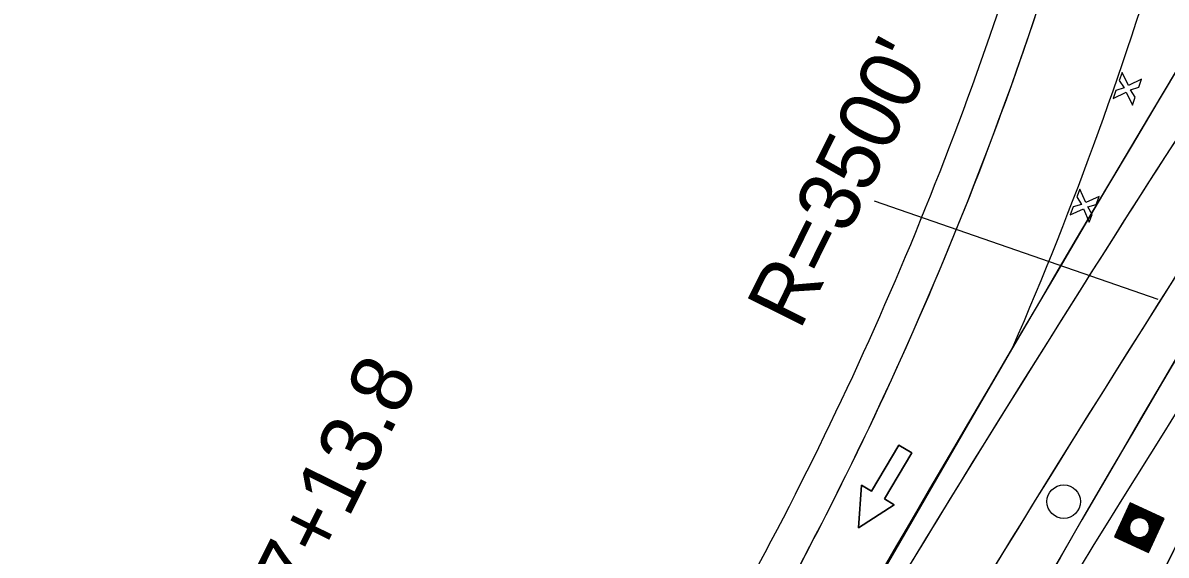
# Model space of a CAD drawing. Extents: x 14104283 to 14129344, y 8637090 to 8673339.
# Drawn here: x 14118812.8 to 14119000.1, y 8668623.1 to 8668710.3 of the extents above; entities that cross this region are included whole.
import ezdxf

# ---------------------------------------------------------------- set-up
doc = ezdxf.new("R2010")
doc.units = 0
for name, color, linetype in [('Cell', 7, 'Continuous'), ('dsnCellElements', 7, 'Continuous'), ('dsnPaintExistingBrokenLaneLineWhite', 7, 'Continuous'), ('dsnPaintExistingChannelizingLaneWhite', 7, 'Continuous'), ('dsnPaintExistingEdgeLineRightWhite', 7, 'Continuous'), ('dsnPaintExistingLaneLineWhite', 7, 'Continuous'), ('dsnShadingPaved', 7, 'Continuous'), ('dsnStdLabel', 7, 'Continuous'), ('dsnStgShadingPrevPav', 7, 'Continuous'), ('dsnTapeExistingChannelizingLaneWhite', 7, 'Continuous'), ('dsnTapeExistingChannelizingLaneYellow', 7, 'Continuous'), ('dsnTapePlaceChannelizingLaneWhite', 7, 'Continuous'), ('dsnTapePlaceChannelizingLaneYellow', 7, 'Continuous'), ('dsnTapeRemoveChannelizingYellow', 7, 'Continuous'), ('Level 2', 7, 'Continuous'), ('Level 5', 7, 'Continuous')]:
    doc.layers.add(name, color=color, linetype=linetype)

msp = doc.modelspace()

# ---------------------------------------------------------------- linework, layer by layer
at = {"layer": 'Cell'}
for p, q in [((14118992.87, 8668702.17), (14118992.42, 8668700.87)), ((14118993.92, 8668700.02), (14118992.87, 8668702.17)), ((14118993.2, 8668699.67), (14118991.85, 8668699.21)), ((14118992.42, 8668700.87), (14118993.2, 8668699.67)), ((14118996.06, 8668701.07), (14118993.92, 8668700.02)), ((14118994.26, 8668699.31), (14118995.61, 8668699.77)), ((14118995.61, 8668699.77), (14118996.06, 8668701.07)), ((14118991.85, 8668699.21), (14118991.4, 8668697.91)), ((14118991.4, 8668697.91), (14118993.55, 8668698.96)), ((14118993.55, 8668698.96), (14118994.6, 8668696.81)), ((14118995.04, 8668698.11), (14118994.26, 8668699.31)), ((14118994.6, 8668696.81), (14118995.04, 8668698.11)), ((14118985.98, 8668683.07), (14118985.49, 8668681.79)), ((14118986.95, 8668680.89), (14118985.98, 8668683.07)), ((14118985.49, 8668681.79), (14118986.22, 8668680.56)), ((14118989.13, 8668681.85), (14118986.95, 8668680.89)), ((14118988.63, 8668680.57), (14118989.13, 8668681.85)), ((14118984.85, 8668680.15), (14118984.36, 8668678.87)), ((14118984.36, 8668678.87), (14118986.54, 8668679.84)), ((14118986.22, 8668680.56), (14118984.85, 8668680.15)), ((14118986.54, 8668679.84), (14118987.51, 8668677.65)), ((14118987.27, 8668680.16), (14118988.63, 8668680.57)), ((14118988, 8668678.94), (14118987.27, 8668680.16)), ((14118987.51, 8668677.65), (14118988, 8668678.94))]:
    msp.add_line(p, q, dxfattribs=at)
msp.add_circle((14118983.32, 8668631.9), 2.75, dxfattribs=at)
at = {"layer": 'dsnCellElements'}
msp.add_circle((14118995.72, 8668627.63), 1.65, dxfattribs=at)
at = {"layer": 'dsnPaintExistingBrokenLaneLineWhite'}
for centre, radius, start, end in [((14121592.11, 8667345.68), 2864.95, 147.15737, 157.1633), ((14121955.85, 8666791.92), 3500, 144.95493, 149.50762)]:
    msp.add_arc(centre, radius, start, end, dxfattribs=at)
at = {"layer": 'dsnPaintExistingChannelizingLaneWhite'}
msp.add_arc((14118409.81, 8668902.17), 616, 336.56541, 343.63038, dxfattribs=at)
at = {"layer": 'dsnPaintExistingEdgeLineRightWhite'}
for centre, radius, start, end in [((14121592.11, 8667345.68), 2852.95, 147.15737, 157.1633), ((14118409.81, 8668902.17), 600, 334.79009, 343.63038), ((14118421.29, 8668896.21), 587.08, 330.32024, 334.83876)]:
    msp.add_arc(centre, radius, start, end, dxfattribs=at)
at = {"layer": 'dsnPaintExistingLaneLineWhite'}
msp.add_arc((14122745.39, 8666422.79), 4382.73, 149.34837, 152.56312, dxfattribs=at)
at = {"layer": 'dsnShadingPaved'}
for centre, radius, start, end in [((14121955.85, 8666791.92), 3512, 144.95493, 152.69211), ((14121955.85, 8666791.92), 3500, 144.95493, 152.69211), ((14121592.11, 8667345.68), 2888.95, 151.24538, 156.90337), ((14118409.81, 8668902.17), 600, 330.3689, 343.63038), ((14121592.11, 8667345.68), 2876.95, 151.24538, 156.90337), ((14118409.81, 8668902.17), 616, 336.56541, 343.63038), ((14123732.96, 8665874.38), 5512, 149.67774, 156.09858)]:
    msp.add_arc(centre, radius, start, end, dxfattribs=at)
at = {"layer": 'dsnStdLabel'}
msp.add_line((14118952.26, 8668681.14), (14118998.75, 8668665.07), dxfattribs=at)
for points in [[(14118997.21, 8668623.56), (14118999.79, 8668629.12), (14118994.23, 8668631.69), (14118991.65, 8668626.13), (14118997.21, 8668623.56)], [(14118997.21, 8668623.56), (14118999.78, 8668629.12), (14118994.23, 8668631.69), (14118991.66, 8668626.14), (14118997.21, 8668623.56)], [(14118997.21, 8668623.56), (14118999.78, 8668629.12), (14118994.23, 8668631.68), (14118991.66, 8668626.14), (14118997.22, 8668623.57)], [(14118997.23, 8668623.7), (14118999.73, 8668629.1), (14118994.25, 8668631.64), (14118991.71, 8668626.15), (14118997.23, 8668623.6)], [(14118997.22, 8668623.75), (14118999.69, 8668629.08), (14118994.26, 8668631.6), (14118991.75, 8668626.17), (14118997.24, 8668623.63)], [(14118997.2, 8668623.79), (14118999.65, 8668629.07), (14118994.28, 8668631.55), (14118991.79, 8668626.19), (14118997.26, 8668623.66)], [(14118997.19, 8668623.83), (14118999.6, 8668629.05), (14118994.29, 8668631.51), (14118991.84, 8668626.2), (14118997.23, 8668623.7)], [(14118997.17, 8668623.88), (14118999.56, 8668629.04), (14118994.31, 8668631.47), (14118991.88, 8668626.22), (14118997.22, 8668623.75)], [(14118997.15, 8668623.92), (14118999.51, 8668629.02), (14118994.33, 8668631.42), (14118991.93, 8668626.23), (14118997.2, 8668623.79)], [(14118997.14, 8668623.97), (14118999.47, 8668629), (14118994.34, 8668631.38), (14118991.97, 8668626.25), (14118997.19, 8668623.83)], [(14118997.12, 8668624.01), (14118999.43, 8668628.99), (14118994.36, 8668631.33), (14118992.01, 8668626.27), (14118997.17, 8668623.88)], [(14118997.11, 8668624.05), (14118999.38, 8668628.97), (14118994.38, 8668631.29), (14118992.06, 8668626.28), (14118997.15, 8668623.92)], [(14118997.09, 8668624.1), (14118999.34, 8668628.96), (14118994.39, 8668631.25), (14118992.1, 8668626.3), (14118997.14, 8668623.97)], [(14118997.07, 8668624.14), (14118999.3, 8668628.94), (14118994.41, 8668631.2), (14118992.14, 8668626.31), (14118997.12, 8668624.01)], [(14118997.06, 8668624.18), (14118999.25, 8668628.92), (14118994.42, 8668631.16), (14118992.19, 8668626.33), (14118997.11, 8668624.05)], [(14118997.04, 8668624.23), (14118999.21, 8668628.91), (14118994.44, 8668631.11), (14118992.23, 8668626.35), (14118997.09, 8668624.1)], [(14118997.03, 8668624.27), (14118999.16, 8668628.89), (14118994.46, 8668631.07), (14118992.28, 8668626.36), (14118997.07, 8668624.14)], [(14118997.01, 8668624.32), (14118999.12, 8668628.87), (14118994.47, 8668631.03), (14118992.32, 8668626.38), (14118997.06, 8668624.18)], [(14118996.99, 8668624.36), (14118999.08, 8668628.86), (14118994.49, 8668630.98), (14118992.36, 8668626.39), (14118997.04, 8668624.23)], [(14118996.98, 8668624.4), (14118999.03, 8668628.84), (14118994.5, 8668630.94), (14118992.41, 8668626.41), (14118997.03, 8668624.27)], [(14118996.96, 8668624.45), (14118998.99, 8668628.83), (14118994.52, 8668630.9), (14118992.45, 8668626.43), (14118997.01, 8668624.32)], [(14118996.95, 8668624.49), (14118998.94, 8668628.81), (14118994.54, 8668630.85), (14118992.49, 8668626.44), (14118996.99, 8668624.36)], [(14118996.93, 8668624.54), (14118998.9, 8668628.79), (14118994.55, 8668630.81), (14118992.54, 8668626.46), (14118996.98, 8668624.4)], [(14118996.91, 8668624.58), (14118998.86, 8668628.78), (14118994.57, 8668630.76), (14118992.58, 8668626.48), (14118996.96, 8668624.45)], [(14118996.9, 8668624.62), (14118998.81, 8668628.76), (14118994.58, 8668630.72), (14118992.63, 8668626.49), (14118996.95, 8668624.49)], [(14118996.88, 8668624.67), (14118998.77, 8668628.75), (14118994.6, 8668630.68), (14118992.67, 8668626.51), (14118996.93, 8668624.54)], [(14118996.86, 8668624.71), (14118998.73, 8668628.73), (14118994.62, 8668630.63), (14118992.71, 8668626.52), (14118996.91, 8668624.58)], [(14118996.85, 8668624.75), (14118998.68, 8668628.71), (14118994.63, 8668630.59), (14118992.76, 8668626.54), (14118996.9, 8668624.62)], [(14118996.83, 8668624.8), (14118998.64, 8668628.7), (14118994.65, 8668630.55), (14118992.8, 8668626.56), (14118996.88, 8668624.67)], [(14118996.82, 8668624.84), (14118998.59, 8668628.68), (14118994.66, 8668630.5), (14118992.85, 8668626.57), (14118996.86, 8668624.71)], [(14118996.8, 8668624.89), (14118998.55, 8668628.67), (14118994.68, 8668630.46), (14118992.89, 8668626.59), (14118996.85, 8668624.75)], [(14118996.78, 8668624.93), (14118998.51, 8668628.65), (14118994.7, 8668630.41), (14118992.93, 8668626.6), (14118996.83, 8668624.8)], [(14118996.77, 8668624.97), (14118998.46, 8668628.63), (14118994.71, 8668630.37), (14118992.98, 8668626.62), (14118996.82, 8668624.84)], [(14118996.75, 8668625.02), (14118998.42, 8668628.62), (14118994.73, 8668630.33), (14118993.02, 8668626.64), (14118996.8, 8668624.89)], [(14118996.74, 8668625.06), (14118998.38, 8668628.6), (14118994.74, 8668630.28), (14118993.06, 8668626.65), (14118996.78, 8668624.93)], [(14118996.72, 8668625.11), (14118998.33, 8668628.59), (14118994.76, 8668630.24), (14118993.11, 8668626.67), (14118996.77, 8668624.97)], [(14118996.7, 8668625.15), (14118998.29, 8668628.57), (14118994.78, 8668630.19), (14118993.15, 8668626.68), (14118996.75, 8668625.02)], [(14118996.69, 8668625.19), (14118998.24, 8668628.55), (14118994.79, 8668630.15), (14118993.2, 8668626.7), (14118996.74, 8668625.06)], [(14118996.67, 8668625.24), (14118998.2, 8668628.54), (14118994.81, 8668630.11), (14118993.24, 8668626.72), (14118996.72, 8668625.11)], [(14118996.66, 8668625.28), (14118998.16, 8668628.52), (14118994.83, 8668630.06), (14118993.28, 8668626.73), (14118996.7, 8668625.15)], [(14118996.64, 8668625.32), (14118998.11, 8668628.51), (14118994.84, 8668630.02), (14118993.33, 8668626.75), (14118996.69, 8668625.19)], [(14118996.62, 8668625.37), (14118998.07, 8668628.49), (14118994.86, 8668629.98), (14118993.37, 8668626.76), (14118996.67, 8668625.24)], [(14118996.61, 8668625.41), (14118998.02, 8668628.47), (14118994.87, 8668629.93), (14118993.41, 8668626.78), (14118996.66, 8668625.28)], [(14118996.59, 8668625.46), (14118997.98, 8668628.46), (14118994.89, 8668629.89), (14118993.46, 8668626.8), (14118996.64, 8668625.32)], [(14118996.58, 8668625.5), (14118997.94, 8668628.44), (14118994.91, 8668629.84), (14118993.5, 8668626.81), (14118996.62, 8668625.37)], [(14118996.56, 8668625.54), (14118997.89, 8668628.42), (14118994.92, 8668629.8), (14118993.55, 8668626.83), (14118996.61, 8668625.41)], [(14118996.11, 8668629.21), (14118994.94, 8668629.76), (14118994.39, 8668628.58)], [(14118995.97, 8668629.24), (14118994.95, 8668629.71), (14118994.48, 8668628.69)], [(14118995.87, 8668629.25), (14118994.97, 8668629.67), (14118994.55, 8668628.77)], [(14118995.78, 8668629.26), (14118994.99, 8668629.63), (14118994.62, 8668628.84)], [(14118995.7, 8668629.26), (14118995, 8668629.58), (14118994.68, 8668628.89)], [(14118995.62, 8668629.26), (14118995.02, 8668629.54), (14118994.74, 8668628.93)], [(14118995.56, 8668629.25), (14118995.03, 8668629.49), (14118994.79, 8668628.97)], [(14118995.49, 8668629.24), (14118995.05, 8668629.45), (14118994.85, 8668629.01)], [(14118995.44, 8668629.24), (14118995.07, 8668629.41), (14118994.9, 8668629.04)], [(14118995.38, 8668629.22), (14118995.08, 8668629.36), (14118994.94, 8668629.06)], [(14118995.33, 8668629.21), (14118995.1, 8668629.32), (14118994.99, 8668629.09)], [(14118995.28, 8668629.2), (14118995.11, 8668629.27), (14118995.04, 8668629.11)], [(14118995.23, 8668629.19), (14118995.13, 8668629.23), (14118995.09, 8668629.13)], [(14118995.18, 8668629.17), (14118995.15, 8668629.19), (14118995.13, 8668629.15)], [(14118997.3, 8668627.23), (14118997.85, 8668628.41), (14118996.67, 8668628.95)], [(14118997.33, 8668627.37), (14118997.81, 8668628.39), (14118996.79, 8668628.86)], [(14118997.35, 8668627.48), (14118997.76, 8668628.38), (14118996.86, 8668628.79)], [(14118997.35, 8668627.57), (14118997.72, 8668628.36), (14118996.93, 8668628.73)], [(14118997.35, 8668627.65), (14118997.67, 8668628.34), (14118996.98, 8668628.67)], [(14118997.35, 8668627.72), (14118997.63, 8668628.33), (14118997.03, 8668628.61)], [(14118997.34, 8668627.79), (14118997.59, 8668628.31), (14118997.06, 8668628.55)], [(14118997.34, 8668627.85), (14118997.54, 8668628.3), (14118997.1, 8668628.5)], [(14118997.33, 8668627.91), (14118997.5, 8668628.28), (14118997.13, 8668628.45)], [(14118997.32, 8668627.97), (14118997.46, 8668628.26), (14118997.16, 8668628.4)], [(14118994.13, 8668628.02), (14118993.59, 8668626.85), (14118994.77, 8668626.3)], [(14118994.11, 8668627.88), (14118993.63, 8668626.86), (14118994.65, 8668626.39)], [(14118994.09, 8668627.77), (14118993.68, 8668626.88), (14118994.57, 8668626.46)], [(14118994.09, 8668627.68), (14118993.72, 8668626.89), (14118994.51, 8668626.53)], [(14118994.09, 8668627.6), (14118993.77, 8668626.91), (14118994.46, 8668626.59)], [(14118994.09, 8668627.53), (14118993.81, 8668626.93), (14118994.41, 8668626.65)], [(14118994.09, 8668627.46), (14118993.85, 8668626.94), (14118994.37, 8668626.7)], [(14118994.1, 8668627.4), (14118993.9, 8668626.96), (14118994.34, 8668626.75)], [(14118994.11, 8668627.34), (14118993.94, 8668626.97), (14118994.31, 8668626.8)], [(14118994.12, 8668627.29), (14118993.98, 8668626.99), (14118994.28, 8668626.85)], [(14118994.13, 8668627.23), (14118994.03, 8668627.01), (14118994.26, 8668626.9)], [(14118994.15, 8668627.18), (14118994.07, 8668627.02), (14118994.23, 8668626.95)], [(14118994.16, 8668627.14), (14118994.12, 8668627.04), (14118994.21, 8668626.99)], [(14118994.18, 8668627.09), (14118994.16, 8668627.05), (14118994.2, 8668627.04)], [(14118996.53, 8668625.63), (14118996.96, 8668626.56)], [(14118996.54, 8668625.59), (14118997.05, 8668626.67)], [(14118997.31, 8668628.02), (14118997.41, 8668628.25), (14118997.18, 8668628.35)], [(14118997.29, 8668628.07), (14118997.37, 8668628.23), (14118997.2, 8668628.31)], [(14118997.28, 8668628.12), (14118997.32, 8668628.22), (14118997.22, 8668628.26)], [(14118997.26, 8668628.16), (14118997.28, 8668628.2), (14118997.24, 8668628.22)], [(14118995.33, 8668626.04), (14118996.59, 8668625.46)], [(14118995.47, 8668626.01), (14118996.58, 8668625.5)], [(14118995.57, 8668626), (14118996.56, 8668625.54)], [(14118995.66, 8668625.99), (14118996.54, 8668625.59)], [(14118995.74, 8668625.99), (14118996.53, 8668625.63)], [(14118995.82, 8668626), (14118996.51, 8668625.67)], [(14118995.88, 8668626), (14118996.49, 8668625.72)], [(14118995.95, 8668626.01), (14118996.48, 8668625.76)], [(14118996, 8668626.02), (14118996.46, 8668625.81)], [(14118996.06, 8668626.03), (14118996.45, 8668625.85)], [(14118996.11, 8668626.04), (14118996.43, 8668625.89)], [(14118996.16, 8668626.05), (14118996.41, 8668625.94)], [(14118996.21, 8668626.07), (14118996.4, 8668625.98)], [(14118996.26, 8668626.08), (14118996.38, 8668626.03)], [(14118996.38, 8668626.03), (14118996.45, 8668626.16)], [(14118996.4, 8668625.98), (14118996.49, 8668626.19)], [(14118996.41, 8668625.94), (14118996.54, 8668626.22)], [(14118996.43, 8668625.89), (14118996.59, 8668626.25)], [(14118996.45, 8668625.85), (14118996.65, 8668626.28)], [(14118996.46, 8668625.81), (14118996.7, 8668626.32)], [(14118996.48, 8668625.76), (14118996.76, 8668626.37)], [(14118996.49, 8668625.72), (14118996.82, 8668626.42)], [(14118996.51, 8668625.67), (14118996.88, 8668626.48)]]:
    msp.add_lwpolyline(points, dxfattribs=at)
for radius in [2864.95, 2842.95]:
    msp.add_arc((14121592.11, 8667345.68), radius, 151.16499, 155.90343, dxfattribs=at)
at = {"layer": 'dsnStgShadingPrevPav'}
for centre, radius, start, end in [((14123732.96, 8665874.38), 5512, 146.42562, 157.1633), ((14123732.59, 8665873.82), 5512, 146.50213, 150.36196), ((14123732.96, 8665874.38), 5488, 146.42119, 157.1633), ((14123732.85, 8665874.2), 5488.01, 146.41277, 150.66874), ((14121592.11, 8667345.68), 2888.95, 147.23666, 156.23389), ((14121592.11, 8667345.68), 2888.95, 147.23666, 155.3184), ((14121592.11, 8667345.68), 2876.95, 147.24009, 156.23389), ((14121574.89, 8667355.29), 2857.26, 147.21534, 155.93843), ((14121574.77, 8667355.07), 2854.28, 147.21105, 155.93334), ((14118409.81, 8668902.17), 594, 330.3689, 343.63038)]:
    msp.add_arc(centre, radius, start, end, dxfattribs=at)
at = {"layer": 'dsnTapeExistingChannelizingLaneWhite'}
for start, end in [(145.38458, 147.96378), (147.96378, 151.97273)]:
    msp.add_arc((14121955.85, 8666791.92), 3512, start, end, dxfattribs=at)
at = {"layer": 'dsnTapeExistingChannelizingLaneYellow'}
msp.add_arc((14121592.11, 8667345.68), 2888.95, 151.25989, 155.3184, dxfattribs=at)
at = {"layer": 'dsnTapePlaceChannelizingLaneWhite'}
msp.add_arc((14121592.11, 8667345.68), 2876.95, 151.24538, 156.90337, dxfattribs=at)
at = {"layer": 'dsnTapePlaceChannelizingLaneYellow'}
for centre, radius, start, end in [((14121955.85, 8666791.92), 3500, 144.95493, 149.50762), ((14121592.11, 8667345.68), 2888.95, 151.24538, 156.90337)]:
    msp.add_arc(centre, radius, start, end, dxfattribs=at)
at = {"layer": 'dsnTapeRemoveChannelizingYellow'}
msp.add_arc((14121955.85, 8666791.92), 3488, 144.95493, 149.50762, dxfattribs=at)
at = {"layer": 'Level 2'}
msp.add_lwpolyline([(14118958.44, 8668639.87), (14118956.29, 8668641.15), (14118951.81, 8668633.63), (14118950.2, 8668634.6), (14118949.68, 8668627.63), (14118955.57, 8668631.39), (14118953.96, 8668632.35)], close=True, dxfattribs=at)
at = {"layer": 'Level 5'}
msp.add_lwpolyline([(14118953.96, 8668632.35), (14118955.57, 8668631.39), (14118949.68, 8668627.63), (14118950.2, 8668634.6), (14118951.81, 8668633.63), (14118956.29, 8668641.15), (14118958.44, 8668639.87), (14118953.96, 8668632.35)], dxfattribs=at)

# ---------------------------------------------------------------- texts
at = {"layer": 'dsnStdLabel'}
for s, p in [("R=3500'", (14118940.06, 8668659.77)), ('PC Sta. 597+13.8', (14118830.59, 8668557.43))]:
    msp.add_text(s, height=10, rotation=63.6002, dxfattribs=at).set_placement(p)

doc.saveas('drawing.dxf')
